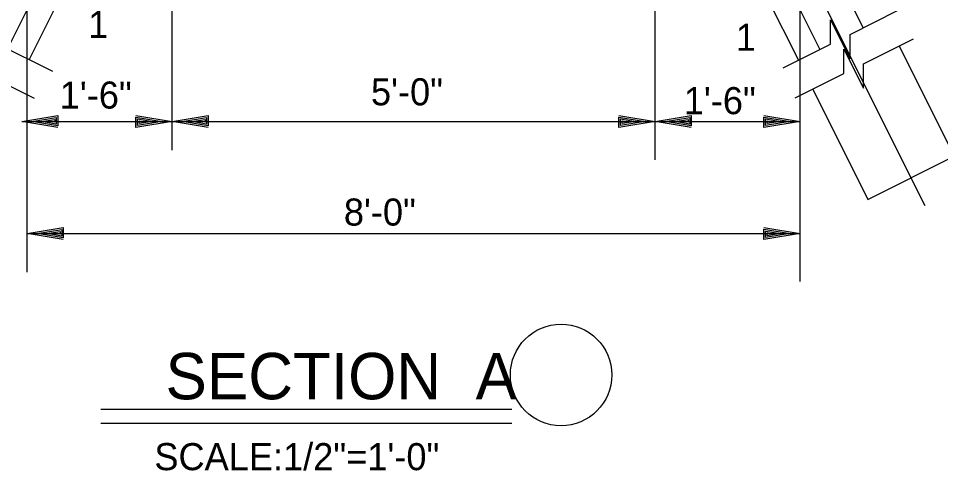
# Model space of a CAD drawing. Extents: x 6 to 106, y 3 to 74.
# Drawn here: x 84.18 to 96.9, y 45.21 to 51.44 of the extents above; entities that cross this region are included whole.
import ezdxf

# ---------------------------------------------------------------- set-up
doc = ezdxf.new("R2010")
doc.units = 0
for name, color, linetype in [('Level 13', 7, 'Continuous'), ('Level 2', 7, 'Continuous'), ('Level 22', 7, 'Continuous'), ('Level 3', 7, 'Continuous'), ('Level 50', 7, 'Continuous')]:
    doc.layers.add(name, color=color, linetype=linetype)

msp = doc.modelspace()

# ---------------------------------------------------------------- linework, layer by layer
at = {"layer": 'Level 13'}
for points in [[(95.383, 51.088), (95.383, 51.423), (95.651, 50.887), (95.651, 51.221)], [(95.568, 50.683), (95.567, 51.018), (95.835, 50.482), (95.835, 50.817)]]:
    msp.add_lwpolyline(points, dxfattribs=at)
at = {"layer": 'Level 22'}
for p, q in [((92.389, 58.198), (95.832, 51.312)), ((87.497, 57.965), (84.026, 51.024)), ((91.76, 57.965), (95.236, 51.014)), ((87.391, 57.009), (84.324, 50.875)), ((91.865, 57.009), (94.938, 50.865)), ((86.295, 49.624), (86.295, 56.307)), ((92.962, 56.307), (96.684, 48.864)), ((92.962, 49.491), (92.962, 56.307)), ((84.295, 47.946), (84.295, 55.628)), ((94.962, 47.814), (94.962, 55.451)), ((95.651, 51.221), (96.316, 51.554)), ((95.835, 50.817), (96.527, 51.162)), ((83.848, 51.112), (84.647, 50.713)), ((94.728, 50.76), (95.383, 51.088)), ((96.329, 51.063), (97.09, 49.541)), ((83.641, 50.719), (84.392, 50.344)), ((94.895, 50.347), (95.568, 50.683)), ((95.136, 50.467), (95.898, 48.944)), ((84.221, 50.021), (86.295, 50.021)), ((86.295, 50.021), (92.962, 50.021)), ((92.962, 50.021), (94.962, 50.021)), ((95.898, 48.944), (97.09, 49.541)), ((84.295, 48.476), (94.962, 48.476)), ((85.314, 46.057), (90.984, 46.057)), ((85.314, 45.863), (90.984, 45.863))]:
    msp.add_line(p, q, dxfattribs=at)
at = {"layer": 'Level 3'}
msp.add_circle((91.664, 46.527), 0.7, dxfattribs=at)
at = {"layer": 'Level 50'}
for p, q in [((84.221, 50.021), (84.221, 50.021)), ((84.359, 50.021), (84.359, 50.021)), ((86.156, 50.021), (86.156, 50.021)), ((86.295, 50.021), (86.295, 50.021)), ((86.295, 50.021), (86.295, 50.021)), ((86.434, 50.021), (86.434, 50.021)), ((92.823, 50.021), (92.823, 50.021)), ((92.962, 50.021), (92.962, 50.021)), ((92.962, 50.021), (92.962, 50.021)), ((93.1, 50.021), (93.1, 50.021)), ((94.823, 50.021), (94.823, 50.021)), ((94.962, 50.021), (94.962, 50.021)), ((84.295, 48.476), (84.295, 48.476)), ((84.434, 48.476), (84.434, 48.476)), ((94.823, 48.476), (94.823, 48.476)), ((94.962, 48.476), (94.962, 48.476))]:
    msp.add_line(p, q, dxfattribs=at)
for points in [[(84.719, 49.938), (84.221, 50.021), (84.719, 50.104), (84.719, 49.962), (84.359, 50.021), (84.698, 50.077), (84.698, 49.986), (84.493, 50.021), (84.677, 50.05), (84.677, 50.013), (84.631, 50.021)], [(85.796, 50.104), (86.295, 50.021), (85.796, 49.938), (85.796, 50.08), (86.156, 50.021), (85.818, 49.965), (85.818, 50.056), (86.023, 50.021), (85.839, 49.992), (85.839, 50.029), (85.884, 50.021)], [(86.794, 49.938), (86.295, 50.021), (86.794, 50.104), (86.794, 49.962), (86.434, 50.021), (86.772, 50.077), (86.772, 49.986), (86.567, 50.021), (86.751, 50.05), (86.751, 50.013), (86.706, 50.021)], [(92.463, 50.104), (92.962, 50.021), (92.463, 49.938), (92.463, 50.08), (92.823, 50.021), (92.484, 49.965), (92.484, 50.056), (92.69, 50.021), (92.506, 49.992), (92.506, 50.029), (92.551, 50.021)], [(93.46, 49.938), (92.962, 50.021), (93.46, 50.104), (93.46, 49.962), (93.1, 50.021), (93.439, 50.077), (93.439, 49.986), (93.234, 50.021), (93.418, 50.05), (93.418, 50.013), (93.372, 50.021)], [(94.463, 50.104), (94.962, 50.021), (94.463, 49.938), (94.463, 50.08), (94.823, 50.021), (94.484, 49.965), (94.484, 50.056), (94.69, 50.021), (94.506, 49.992), (94.506, 50.029), (94.551, 50.021)], [(84.794, 48.393), (84.295, 48.476), (84.794, 48.559), (84.794, 48.417), (84.434, 48.476), (84.772, 48.532), (84.772, 48.441), (84.567, 48.476), (84.751, 48.505), (84.751, 48.468), (84.706, 48.476)], [(94.463, 48.559), (94.962, 48.476), (94.463, 48.393), (94.463, 48.535), (94.823, 48.476), (94.484, 48.42), (94.484, 48.511), (94.69, 48.476), (94.506, 48.447), (94.506, 48.484), (94.551, 48.476)]]:
    msp.add_lwpolyline(points, dxfattribs=at)

# ---------------------------------------------------------------- texts
at = {"layer": 'Level 2'}
msp.add_text('SECTION  A  ', height=0.63999, dxfattribs=at).set_placement((86.205, 46.191))
at = {"layer": 'Level 22'}
for s, height, p in [('1', 0.373, (85.137, 51.172)), ('1', 0.373, (94.075, 50.996)), ('1\'-6"', 0.3733, (84.745, 50.199)), ('5\'-0"', 0.3733, (89.04, 50.244)), ('1\'-6"', 0.3733, (93.357, 50.122)), ('8\'-0"', 0.3733, (88.666, 48.586)), ('SCALE:1/2"=1\'-0"', 0.37333, (86.051, 45.214))]:
    msp.add_text(s, height=height, dxfattribs=at).set_placement(p)

doc.saveas('drawing.dxf')
